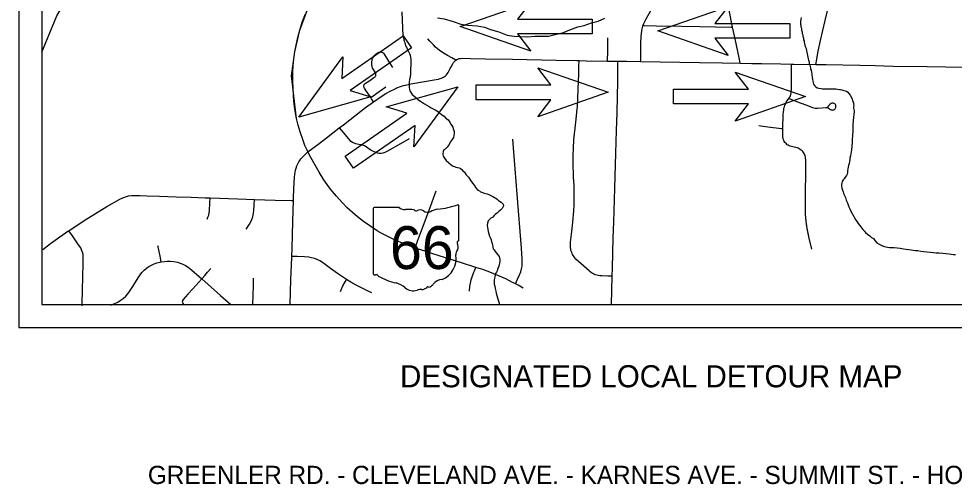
# Model space of a CAD drawing. Extents: x -483 to 680, y 0 to 440.
# Drawn here: x 436.4 to 580.4, y 219 to 290.7 of the extents above; entities that cross this region are included whole.
import ezdxf

# ---------------------------------------------------------------- set-up
doc = ezdxf.new("R2010")
doc.units = 0
for name, color, linetype in [('Default', 7, 'Continuous'), ('GM_X_City_Street', 7, 'Continuous'), ('GM_X_County_Road', 7, 'Continuous'), ('GM_X_Major_River', 7, 'Continuous'), ('GM_X_Minor_River', 7, 'Continuous'), ('GM_X_State_Route', 7, 'Continuous'), ('GM_X_State_Shield', 7, 'Continuous'), ('GM_X_Township_Road', 7, 'Continuous'), ('SH_Text', 7, 'Continuous')]:
    doc.layers.add(name, color=color, linetype=linetype)

msp = doc.modelspace()

# ---------------------------------------------------------------- linework, layer by layer
at = {"layer": 'Default'}
msp.add_lwpolyline([(436.43, 419.53), (436.43, 243.16), (629.12, 243.16), (629.12, 419.53)], close=True, dxfattribs=at)
msp.add_lwpolyline([(479.18, 275.33), (478.41, 281.87), (478.89, 285.56), (479.68, 288.94), (481.01, 292.52)], dxfattribs=at)
at = {"layer": 'GM_X_City_Street'}
msp.add_line((446.17, 246.5), (446.17, 246.58), dxfattribs=at)
for points in [[(532.11, 284.11), (532.12, 284.35), (532.14, 285.34), (532.14, 286.89), (532.19, 288), (532.23, 288.37), (532.29, 288.79), (532.35, 289.11), (532.41, 289.35), (532.51, 289.66), (532.63, 289.96), (532.98, 290.68), (533.88, 292.31), (534.84, 294.06), (535.27, 294.83), (536.17, 296.45), (539.57, 302.59), (540.98, 305.15), (542.08, 307.09), (542.51, 307.85), (544.46, 311.4), (545.32, 312.98), (546.62, 315.33), (547.54, 317.01)], [(547.44, 283.84), (547.26, 284.67), (546.66, 287.59), (546.27, 289.4), (545.72, 291.97), (544.63, 297.02), (544.39, 298.17), (543.75, 301.28), (543.31, 303.41), (542.7, 306.19), (542.62, 306.4), (542.51, 306.61), (542.24, 306.92), (542.08, 307.09)], [(559.05, 283.63), (559.1, 283.89), (559.44, 285.68), (559.8, 287.32), (560.51, 290.4), (561.5, 294.5), (561.68, 295.27)], [(532.51, 289.66), (532.65, 289.65), (534.52, 289.59), (538.36, 289.54), (541.22, 289.48), (546.02, 289.4), (546.27, 289.4)], [(503.67, 284.3), (503.09, 284.67), (502.41, 285.04), (501.78, 285.39), (501.44, 285.63), (501.18, 285.81), (500.82, 286.09), (500.56, 286.32), (500.23, 286.64), (500.03, 286.84), (499.69, 287.22), (499.38, 287.59)], [(527.04, 284.16), (527.04, 284.31), (527.07, 285.56), (527.09, 286.76), (527.07, 287.75)], [(490.6, 278.54), (489.76, 279.75), (489.62, 280.01), (489.57, 280.1), (489.54, 280.2), (489.53, 280.32), (489.54, 280.4), (489.56, 280.48), (489.59, 280.56), (489.65, 280.64), (490.45, 281.19), (491.07, 281.61), (491.25, 281.74), (491.31, 281.82), (491.35, 281.9), (491.38, 282), (491.38, 282.1), (491.37, 282.19), (491.35, 282.28), (491.33, 282.36), (490.99, 282.85), (490.86, 283.1), (490.82, 283.2), (490.79, 283.31), (490.76, 283.47), (490.75, 283.62), (490.74, 283.77), (490.75, 283.93), (490.75, 284.03), (490.77, 284.14), (490.79, 284.26), (490.83, 284.39), (490.88, 284.55), (490.94, 284.69), (491, 284.82), (491.06, 284.92), (491.12, 285), (491.2, 285.09), (491.28, 285.16), (491.4, 285.26), (491.85, 285.52), (491.96, 285.55), (492.06, 285.56), (492.14, 285.56), (492.24, 285.55), (492.33, 285.53), (492.42, 285.49), (492.48, 285.44), (492.57, 285.35), (493.94, 283.15)], [(527.74, 251.08), (527.07, 251.08), (526.14, 251.09), (525.87, 251.12), (525.62, 251.15), (525.38, 251.21), (525.14, 251.29), (524.93, 251.37), (524.75, 251.48), (524.56, 251.59), (524.36, 251.71), (524.17, 251.87), (522.14, 253.7), (521.99, 253.89), (521.87, 254.05), (521.76, 254.21), (521.63, 254.42), (521.56, 254.6), (521.47, 254.82), (521.39, 255.02), (521.35, 255.24), (521.32, 255.45), (521.3, 255.65), (521.3, 255.81), (521.32, 256.3), (521.51, 257.96), (521.66, 259.39), (521.82, 261.12), (521.88, 262.06), (521.9, 263.18), (521.87, 265.05), (521.81, 266.23), (521.73, 268.59), (521.74, 269.64), (521.77, 270.76), (521.86, 272.06), (522.14, 274.78), (522.29, 276.27), (522.36, 276.82), (522.38, 277.13), (522.52, 279.86), (522.59, 282.22), (522.62, 283.34), (522.66, 284.23)], [(527.61, 246.7), (527.74, 251.08), (527.77, 252.29), (527.91, 256.96), (527.99, 259.38), (528.16, 264.6), (528.31, 270.01), (528.4, 273.5), (528.5, 276.23), (528.62, 281.08), (528.63, 283.13), (528.63, 284.15)], [(558.48, 255.21), (558, 257.12), (557.99, 257.19), (557.97, 257.25), (557.96, 257.32), (557.94, 257.38), (557.93, 257.45), (557.91, 257.52), (557.9, 257.58), (557.88, 257.65), (557.87, 257.71), (557.86, 257.78), (557.84, 257.85), (557.83, 257.91), (557.82, 257.98), (557.8, 258.04), (557.79, 258.11), (557.78, 258.18), (557.77, 258.24), (557.75, 258.31), (557.74, 258.38), (557.73, 258.44), (557.72, 258.51), (557.71, 258.58), (557.7, 258.64), (557.69, 258.71), (557.68, 258.78), (557.67, 258.84), (557.66, 258.91), (557.65, 258.98), (557.64, 259.04), (557.63, 259.11), (557.62, 259.18), (557.61, 259.24), (557.6, 259.31), (557.59, 259.38), (557.59, 259.44), (557.58, 259.51), (557.57, 259.58), (557.56, 259.65), (557.56, 259.71), (557.55, 259.78), (557.54, 259.85), (557.54, 259.91), (557.53, 259.98), (557.52, 260.05), (557.52, 260.12), (557.51, 260.18), (557.51, 260.25), (557.5, 260.32), (557.5, 260.39), (557.5, 260.45), (557.49, 260.52), (557.49, 260.59), (557.48, 260.66), (557.48, 260.72), (557.48, 260.79), (557.47, 260.86), (557.47, 260.92), (557.47, 260.99), (557.47, 261.06), (557.46, 261.13), (557.46, 261.19), (557.46, 261.26), (557.46, 261.33), (557.46, 261.4), (557.46, 261.46), (557.46, 261.53), (557.46, 261.6), (557.46, 261.67), (557.46, 261.73), (557.46, 261.8), (557.46, 261.87), (557.46, 261.94), (557.46, 262), (557.52, 268.84), (557.48, 269.32), (557.41, 269.61), (557.35, 269.76), (557.27, 269.93), (557.17, 270.08), (557.06, 270.22), (556.96, 270.34), (556.81, 270.47), (556.68, 270.57), (556.52, 270.68), (556.35, 270.76), (556.2, 270.82), (555.55, 270.98), (555.12, 271.09), (554.96, 271.14), (554.82, 271.2), (554.67, 271.29), (554.55, 271.41), (554.32, 271.65), (554.21, 271.79), (554.15, 271.93), (554.09, 272.06), (554.03, 272.24), (554, 272.38), (553.98, 272.56), (553.99, 273.32), (554.01, 273.78), (554.06, 275.99), (554.08, 276.31), (554.13, 276.68), (554.17, 276.9), (554.23, 277.11), (554.3, 277.34), (554.41, 277.59), (554.52, 277.81), (554.66, 278.03), (554.93, 278.42), (555.05, 278.58), (555.17, 278.85), (555.22, 279.04), (555.26, 279.25), (555.29, 279.47), (555.31, 279.74), (555.35, 283.46), (555.35, 283.7)], [(490.6, 278.54), (490.97, 278.81), (491.88, 279.49), (492.92, 280.21)], [(491.03, 277.91), (490.71, 278.37), (490.6, 278.54)], [(554.93, 278.42), (555.08, 278.36), (556.64, 277.74), (557.67, 277.35), (558.55, 277.02), (558.74, 276.97), (558.96, 276.93), (559.14, 276.9), (559.32, 276.91), (560.62, 277.04), (560.83, 277.02), (561.03, 276.93), (561.35, 276.73), (561.44, 276.68), (561.53, 276.64), (561.62, 276.63), (561.74, 276.64), (561.85, 276.67), (561.93, 276.73), (562.02, 276.8), (562.11, 276.92), (562.14, 277), (562.16, 277.13), (562.16, 277.29), (562.14, 277.38), (562.1, 277.46), (562.01, 277.56), (561.88, 277.63), (561.77, 277.67), (561.66, 277.68), (561.53, 277.67), (561.41, 277.61), (561.28, 277.52), (561.19, 277.44), (561.11, 277.35), (561.01, 277.25), (560.85, 277.07)], [(485.73, 273.87), (486.33, 273.17), (487.17, 272.17), (487.39, 271.96), (487.62, 271.78), (487.88, 271.63), (488.22, 271.5), (488.75, 271.38), (489.12, 271.31), (489.43, 271.23), (489.73, 271.1), (490.11, 270.87), (490.66, 270.46), (490.98, 270.28), (491.31, 270.14), (491.6, 270.06), (491.89, 270.01), (492.19, 270.01), (492.48, 270.05), (492.83, 270.15), (493.21, 270.33), (495.21, 271.46), (496.55, 272.25)], [(550.31, 274.22), (550.61, 274.19), (551.71, 274.06), (553.8, 273.8), (554.01, 273.78)], [(512.85, 249.88), (513.18, 250.58), (513.5, 251.25), (513.67, 251.71), (513.8, 252.18), (513.87, 252.6), (513.9, 253.09), (513.88, 253.7), (513.77, 255.37), (513.12, 263.68), (512.81, 267.59), (512.6, 270.13), (512.47, 272.12)], [(440.12, 255.18), (441.31, 256.07), (442.73, 257.09), (444, 257.97), (444.14, 258.06), (446.49, 259.61), (448.23, 260.7), (449.98, 261.76), (451.98, 262.9), (452.47, 263.14), (452.87, 263.29), (453.34, 263.41), (453.76, 263.47), (454.25, 263.49), (455.05, 263.47), (456.17, 263.43), (458.1, 263.35), (460.64, 263.28), (462.94, 263.21), (465.11, 263.14), (465.86, 263.11), (470.15, 262.97), (472.68, 262.88), (475.86, 262.77), (478.42, 262.7), (478.71, 262.69)], [(497.4, 255.39), (497.8, 256.47), (498.39, 258.11), (499.56, 261.24), (500.68, 264.2)], [(465.4, 259.84), (465.52, 260.12), (465.66, 260.47), (465.75, 260.82), (465.79, 261.19), (465.83, 262.3), (465.86, 263.11)], [(471.44, 258.3), (471.95, 259.08), (472.13, 259.4), (472.3, 259.8), (472.43, 260.21), (472.56, 260.76), (472.62, 261.19), (472.65, 262.05), (472.68, 262.88)], [(446.17, 246.64), (446.23, 249.16), (446.27, 250.7), (446.35, 253.26), (446.36, 254.01), (446.33, 254.39), (446.24, 254.77), (446.11, 255.13), (445.96, 255.42), (445.65, 255.89), (444.69, 257.27), (444.14, 258.06)], [(458.36, 253.26), (458.18, 254.15), (457.89, 255.55), (457.85, 255.73)], [(450.61, 246.62), (450.8, 246.68), (451.2, 246.83), (451.69, 247.08), (452.06, 247.3), (452.5, 247.63), (452.91, 248), (453.19, 248.32), (453.48, 248.71), (453.98, 249.49), (454.78, 250.83), (455.1, 251.29), (455.39, 251.64), (455.74, 252), (456.09, 252.28), (456.45, 252.53), (456.85, 252.75), (457.25, 252.94), (457.68, 253.09), (458.17, 253.22), (458.36, 253.26), (458.85, 253.34), (459.29, 253.38), (459.74, 253.37), (460.3, 253.31), (460.86, 253.2), (461.29, 253.08), (461.7, 252.92), (462.1, 252.71), (462.52, 252.44), (463.02, 252.06), (464.59, 250.67), (467.47, 248.07), (469.04, 246.7)], [(490.75, 248.49), (490.2, 248.73), (488.37, 249.67), (487.55, 250.12), (486.86, 250.55), (486.38, 250.84), (485.45, 251.46), (484.38, 252.22), (483.15, 253.15), (482.74, 253.42), (482.36, 253.61), (481.96, 253.76), (481.49, 253.89), (481.07, 253.97), (480.4, 254.03), (479.28, 254.08), (479.03, 254.08), (478.44, 254.1)], [(464.59, 250.67), (465.04, 251.18), (465.49, 251.68), (465.98, 252.24)], [(505.78, 248.75), (505.78, 248.76), (505.84, 249.51), (505.92, 250.01), (506.04, 250.5), (506.25, 251.09), (506.47, 251.67), (506.55, 251.9), (506.74, 252.42)], [(464.59, 250.67), (463.2, 249.11), (462.45, 248.27), (461.75, 247.48), (461.65, 247.32), (461.61, 247.21), (461.6, 247.08), (461.63, 246.96), (461.8, 246.7)], [(472.44, 246.7), (472.54, 249.59), (472.54, 250.77)], [(485.96, 248.69), (486.04, 248.94), (486.31, 249.57), (486.66, 250.2), (486.86, 250.55)]]:
    msp.add_lwpolyline(points, dxfattribs=at)
at = {"layer": 'GM_X_County_Road'}
for points in [[(491.03, 277.91), (492.18, 278.69), (492.92, 279.15), (493.68, 279.58), (494.12, 279.81), (494.58, 280.02), (495.17, 280.24), (495.64, 280.39), (496.13, 280.52), (496.74, 280.66), (500.63, 281.3), (500.99, 281.37), (501.28, 281.46), (501.56, 281.58), (501.78, 281.68), (501.94, 281.79), (502.09, 281.91), (502.22, 282.04), (502.33, 282.19), (502.48, 282.39), (502.7, 282.81), (502.82, 283.01), (502.96, 283.29), (503.2, 283.72), (503.34, 283.94), (503.67, 284.3)], [(503.67, 284.3), (503.92, 284.43), (504.11, 284.5), (504.21, 284.53), (504.38, 284.56), (504.65, 284.59), (505.92, 284.57), (508.25, 284.52), (512.41, 284.43), (516.89, 284.33), (519.13, 284.29), (522.29, 284.24), (522.66, 284.23)], [(522.66, 284.23), (523.72, 284.2), (527.04, 284.16)], [(527.04, 284.16), (527.45, 284.15), (528.63, 284.15)], [(528.63, 284.15), (529.94, 284.15), (532.11, 284.11)], [(532.11, 284.11), (541.19, 283.95), (544.67, 283.88), (547.44, 283.84)], [(547.44, 283.84), (549.21, 283.81), (550.7, 283.77), (553.68, 283.73), (555.35, 283.7)], [(555.35, 283.7), (555.67, 283.69), (559.05, 283.63)], [(559.05, 283.63), (560.64, 283.61), (565.86, 283.51), (568.22, 283.46), (570.95, 283.4), (576.18, 283.32), (584.63, 283.16), (587.24, 283.1), (589.24, 283.03), (593.07, 282.9)], [(485.73, 273.87), (486.38, 274.37), (488.35, 275.89), (489.78, 276.99), (491.03, 277.91)], [(480.93, 270.18), (482.65, 271.47), (483.78, 272.34), (485.73, 273.87)]]:
    msp.add_lwpolyline(points, dxfattribs=at)
at = {"layer": 'GM_X_Major_River'}
for points in [[(439.96, 285.51), (442.31, 291.1), (442.99, 292.37), (443.71, 293.71), (444.39, 294.8), (444.99, 295.88), (445.55, 297), (446.07, 298.01), (446.59, 298.99)], [(500.86, 290.81), (501.88, 290.67), (503.28, 290.25), (504.44, 289.84), (505.5, 289.7), (506.94, 289.59), (508.07, 289.37), (509.04, 289.04), (510.32, 288.67), (511.56, 288.14), (512.66, 288), (513.68, 287.93), (514.66, 287.91), (515.84, 287.99), (516.98, 288), (517.96, 288.01), (518.96, 288.25), (520.25, 288.56), (521.21, 288.95), (522.47, 289.42), (523.43, 289.62), (524.58, 290.05), (525.57, 290.29), (526.61, 290.75)]]:
    msp.add_lwpolyline(points, dxfattribs=at)
at = {"layer": 'GM_X_Minor_River'}
for points in [[(495.38, 291.75), (495.51, 288.01), (495.62, 287.77), (495.68, 287.39), (495.75, 287.2), (495.82, 287.01), (495.89, 286.74), (495.96, 286.51), (496.07, 286.28), (496.18, 286.05), (496.28, 285.82), (496.46, 285.51), (496.54, 285.32), (496.64, 285.05), (496.71, 284.7), (496.74, 284.47), (496.76, 284.05), (496.75, 283.48), (496.73, 283.03), (496.72, 282.65), (496.71, 282.15), (496.66, 281.81), (496.62, 281.55), (496.57, 281.25), (496.52, 280.94), (496.51, 280.68), (496.51, 280.37), (496.5, 280.11), (496.53, 279.8), (496.6, 279.57), (496.96, 279.03), (497.22, 278.83), (497.52, 278.56), (497.85, 278.24), (498.26, 278), (498.56, 277.8), (498.86, 277.57), (499.23, 277.37), (499.57, 277.17), (499.9, 276.97), (500.2, 276.81), (500.5, 276.65), (500.76, 276.49), (500.99, 276.37), (501.17, 276.21), (501.43, 276.01), (501.65, 275.85), (501.88, 275.66), (502.1, 275.42), (502.32, 275.26), (502.51, 275.11), (502.76, 274.76), (502.87, 274.49), (503.05, 274.22), (503.2, 273.98), (503.3, 273.64), (503.4, 273.33), (503.43, 272.99), (503.39, 272.72), (503.3, 272.42), (502.98, 271.9), (502.82, 271.67), (502.66, 271.34), (502.35, 270.93), (502.03, 270.59), (501.84, 270.49), (501.72, 270.22), (501.67, 269.84), (501.74, 269.54), (501.92, 269.23), (502.21, 268.88), (502.54, 268.56), (502.95, 268.21), (503.25, 268.01), (503.48, 267.93), (503.7, 267.81), (503.96, 267.76), (504.19, 267.72), (504.38, 267.64), (504.6, 267.48), (504.75, 267.28), (505.01, 267.05), (505.26, 266.66), (505.63, 266.31), (505.89, 265.88), (506.1, 265.57), (506.29, 265.34), (506.43, 265.14), (506.65, 264.87), (506.69, 264.68), (507.09, 264.29), (507.32, 264.17), (507.5, 264.05), (507.69, 263.97), (508.03, 263.84), (508.25, 263.76)], [(556.82, 290.88), (556.78, 290.58), (556.73, 290.28), (556.72, 290.05), (556.72, 289.86), (556.75, 289.67), (556.78, 289.44), (556.85, 289.21), (556.88, 288.94), (556.95, 288.67), (556.98, 288.41), (557.05, 288.18), (557.08, 287.95), (557.15, 287.68), (557.18, 287.45), (557.25, 287.26), (557.28, 287.07), (557.45, 286.41), (557.56, 286.07), (557.63, 285.76), (557.69, 285.53), (557.72, 285.27), (557.79, 285), (557.82, 284.77), (557.89, 284.5), (557.96, 284.31), (558.03, 284.04), (558.06, 283.77), (558.13, 283.54), (558.2, 283.31), (558.23, 283.12), (558.26, 282.93), (558.34, 282.74), (558.4, 282.4), (558.43, 282.2), (558.47, 282.01), (558.53, 281.67), (558.56, 281.33), (558.59, 281.13), (558.66, 280.79), (558.73, 280.6), (558.84, 280.41), (559.06, 280.17), (559.28, 280.05), (559.51, 279.97), (559.89, 279.92)], [(559.89, 279.92), (560.11, 279.91), (560.34, 279.91), (560.57, 279.9), (560.91, 279.89), (561.29, 279.88), (561.52, 279.91), (562.13, 279.89), (562.39, 279.85), (562.69, 279.8), (562.88, 279.76), (563.07, 279.71), (563.37, 279.63), (563.56, 279.59), (563.79, 279.54), (564.01, 279.38), (564.16, 279.19), (564.34, 278.92), (564.56, 278.53), (564.66, 278.3), (564.73, 278.11), (564.84, 277.72), (564.87, 277.53), (564.9, 277.3), (564.89, 277.11), (564.89, 276.92), (564.92, 276.69), (564.95, 276.5), (564.95, 276.31), (564.94, 276.05), (564.93, 275.86), (564.89, 275.63), (564.84, 275.37), (564.8, 275.1), (564.79, 274.83), (564.78, 274.57), (564.77, 274.15), (564.76, 273.88), (564.75, 273.58), (564.74, 273.24), (564.7, 272.9), (564.69, 272.56), (564.68, 272.25), (564.67, 271.95), (564.66, 271.64), (564.55, 270.51), (564.5, 270.17), (564.46, 269.86), (564.41, 269.56), (564.32, 269.22), (564.28, 268.96), (564.23, 268.73), (564.19, 268.39), (564.1, 268.09), (564.06, 267.82), (564.01, 267.59), (563.96, 267.29), (563.92, 266.95), (563.87, 266.76), (563.79, 266.57), (563.59, 266.28), (563.43, 266.05), (563.28, 265.87), (563.12, 265.64), (563.07, 265.42), (563.03, 265.15), (563.02, 264.89), (563.05, 264.58), (563.16, 264.27), (563.26, 264.04), (563.33, 263.85), (563.4, 263.66), (563.55, 263.35), (563.62, 263.16), (563.69, 262.97), (563.76, 262.77), (563.9, 262.43), (564.04, 262.04), (564.15, 261.74), (564.29, 261.43), (564.43, 261.08), (564.94, 260.23), (565.08, 259.96), (565.23, 259.69), (565.41, 259.42), (565.59, 259.18), (565.77, 258.91), (565.99, 258.64), (566.14, 258.45), (566.29, 258.25), (566.54, 257.98), (566.73, 257.78), (567.02, 257.51), (567.36, 257.27), (567.66, 257.03), (567.92, 256.84), (568.13, 256.53), (568.47, 256.21), (568.84, 255.97), (569.14, 255.81), (569.33, 255.73)], [(508.25, 263.76), (508.52, 263.72), (508.74, 263.63), (508.97, 263.51), (509.19, 263.43), (509.38, 263.31), (509.64, 263.19), (509.83, 263.07), (510.02, 262.91), (510.2, 262.75), (510.42, 262.6), (510.65, 262.44), (510.98, 262.12), (511.01, 261.86), (510.81, 261.48), (510.57, 261.22), (510.3, 261), (510.03, 260.78), (509.8, 260.6), (509.6, 260.38), (509.37, 260.16), (509.06, 259.97), (508.86, 259.79), (508.66, 259.57), (508.54, 259.23), (508.49, 258.85), (508.56, 258.54), (508.59, 258.28), (508.66, 257.93), (508.76, 257.59), (508.86, 257.24), (509.01, 256.93), (509.11, 256.63), (509.18, 256.4), (509.29, 256.09), (509.32, 255.86), (509.38, 255.52), (509.45, 255.29), (509.56, 255.09), (509.71, 254.86), (509.93, 254.59), (510.15, 254.35), (510.33, 254.08), (510.4, 253.89), (510.43, 253.62), (510.46, 253.32), (510.32, 252.6), (510.16, 252.22), (510.04, 251.88), (509.92, 251.7), (509.8, 251.47), (509.71, 251.17), (509.67, 250.94), (509.63, 250.76), (509.58, 250.45), (509.57, 250.15), (509.6, 249.84), (509.67, 249.54), (509.73, 249.16), (509.83, 248.77), (509.9, 248.43), (510, 248.08), (510.38, 246.7)], [(569.33, 255.73), (569.63, 255.61), (569.82, 255.56), (570.12, 255.52), (570.38, 255.47), (570.61, 255.47), (570.84, 255.46), (571.14, 255.49), (571.56, 255.44), (572.05, 255.35), (572.54, 255.26), (572.96, 255.21), (573.37, 255.16), (574.43, 255.01), (574.78, 255), (575.23, 254.91), (575.68, 254.86), (576.17, 254.81), (576.67, 254.76), (577.12, 254.71), (577.58, 254.66), (578.07, 254.64), (578.6, 254.59), (579.09, 254.54), (579.58, 254.49), (580.19, 254.39), (580.57, 254.38)]]:
    msp.add_lwpolyline(points, dxfattribs=at)
at = {"layer": 'GM_X_State_Route'}
msp.add_lwpolyline([(514.04, 249.19), (513.25, 249.67), (512.85, 249.88), (512.42, 250.11), (511.35, 250.64), (510.15, 251.18), (508.93, 251.67), (507.81, 252.08), (506.74, 252.42), (504.55, 253.13), (500.12, 254.5), (498.44, 255.04), (497.4, 255.39), (497.04, 255.52), (495.49, 256.12), (494.35, 256.6), (493.41, 257.05), (492.38, 257.6), (491.58, 258.06), (490.45, 258.8), (489.49, 259.47), (488.57, 260.19), (487.76, 260.86), (486.95, 261.6), (486.17, 262.39), (485.3, 263.35), (484.41, 264.43), (483.38, 265.91), (482.65, 267.06), (482.02, 268.13), (481.36, 269.32), (480.93, 270.18), (480.8, 270.43), (480.47, 271.15), (480.17, 271.96), (479.74, 273.25), (479.42, 274.32), (479.18, 275.33), (479, 276.2), (478.91, 276.82), (478.76, 277.97), (478.69, 278.85), (478.63, 279.99), (478.6, 281.08), (478.6, 282.41), (478.64, 283.41), (478.75, 284.52), (478.89, 285.56), (479.09, 286.6), (479.37, 287.81), (479.68, 288.94), (480.05, 290.12), (480.55, 291.43)], dxfattribs=at)
at = {"layer": 'GM_X_State_Shield'}
for p, q in [((490.97, 261.46), (490.97, 251.45)), ((494.96, 261.63), (491.1, 261.63)), ((504.16, 256.64), (504.16, 261.88)), ((504.16, 256.64), (504.16, 256.64))]:
    msp.add_line(p, q, dxfattribs=at)
for centre, radius, start, end in [((499.46, 275.27), 13.98, 275.8445, 288.9065), ((504.01, 261.9), 0.147, 351.8621, 97.738), ((491.13, 261.48), 0.153, 98.1301, 188.1301), ((495.88, 262.79), 1.48, 231.6195, 271.1119), ((496.38, 256.01), 5.32, 80.4867, 94.9883), ((497.58, 261.53), 0.427, 219.7921, 297.1024), ((498.21, 260.37), 0.889, 54.4667, 119.1411), ((499.36, 261.96), 1.07, 233.8562, 294.8282), ((501.24, 258.57), 2.81, 97.3462, 120.7689), ((504.12, 256.26), 0.227, 107.944, 210.337), ((504, 256.62), 0.157, 289.6038, 7.7341), ((504.68, 254.45), 0.992, 136.8065, 186.9296), ((502.68, 255.6), 1.36, 340.033, 23.6496), ((500.24, 253.79), 3.5, 292.3089, 8.9858), ((491.13, 251.43), 0.154, 171.9584, 258.3066), ((491.15, 252.45), 1.18, 267.339, 280.6039), ((491.39, 250.87), 0.424, 29.7484, 93.2717), ((496.74, 259.86), 10.1, 240.4129, 257.1985), ((501.72, 248.64), 1.92, 94.4031, 142.5768), ((493.73, 246.96), 3.16, 47.1842, 75.836), ((497.15, 250.82), 2, 230.7004, 286.2918), ((498.45, 250.08), 1.07, 268.777, 315.5493), ((499.42, 249.11), 0.301, 65.7517, 132.6484), ((499.29, 250.48), 1.13, 282.8732, 323.2771), ((498.31, 247.37), 1.65, 85.6951, 111.2099)]:
    msp.add_arc(centre, radius, start, end, dxfattribs=at)
at = {"layer": 'GM_X_Township_Road'}
for points in [[(479.21, 268.03), (479.3, 268.24), (479.4, 268.46), (479.52, 268.65), (479.66, 268.86), (479.85, 269.1), (480, 269.26), (480.93, 270.18)], [(478.71, 262.69), (478.73, 263.07), (478.78, 264.56), (478.87, 266.28), (478.91, 266.69), (478.95, 267.06), (479.01, 267.38), (479.1, 267.68), (479.21, 268.03)], [(478.44, 254.1), (478.49, 255.31), (478.61, 259.47), (478.71, 262.69)], [(478.17, 246.7), (478.31, 250.53), (478.44, 253.88), (478.44, 254.1)]]:
    msp.add_lwpolyline(points, dxfattribs=at)
at = {"layer": 'SH_Text'}
for p, q in [((504.36, 289.47), (515.2, 293.23)), ((515.2, 293.23), (513.17, 290.59)), ((534.74, 288.8), (545.58, 292.57)), ((534.74, 288.8), (545.58, 292.57)), ((545.58, 292.57), (543.54, 289.93)), ((545.58, 292.57), (543.54, 289.93)), ((515.2, 285.7), (504.36, 289.47)), ((513.17, 290.59), (524.68, 290.59)), ((524.68, 290.59), (524.68, 288.34)), ((543.54, 289.93), (555.06, 289.93)), ((543.54, 289.93), (555.06, 289.93)), ((555.06, 289.93), (555.06, 287.68)), ((555.06, 289.93), (555.06, 287.68)), ((486.13, 281.5), (495.59, 288.06)), ((495.59, 288.06), (496.88, 286.21)), ((524.68, 288.34), (513.17, 288.34)), ((513.17, 288.34), (515.2, 285.7)), ((545.58, 285.04), (534.74, 288.8)), ((545.58, 285.04), (534.74, 288.8)), ((555.06, 287.68), (543.54, 287.68)), ((543.54, 287.68), (545.58, 285.04)), ((555.06, 287.68), (543.54, 287.68)), ((543.54, 287.68), (545.58, 285.04)), ((496.88, 286.21), (487.42, 279.64)), ((479.54, 275.55), (486.3, 284.82)), ((486.3, 284.82), (486.13, 281.5)), ((516.28, 283.11), (527.12, 279.35)), ((518.32, 280.48), (516.28, 283.11)), ((546.66, 282.45), (557.5, 278.69)), ((548.69, 279.82), (546.66, 282.45)), ((546.66, 282.45), (557.5, 278.69)), ((548.69, 279.82), (546.66, 282.45)), ((487.42, 279.64), (490.59, 278.64)), ((492.95, 277.13), (504, 280.22)), ((504, 280.22), (497.24, 270.94)), ((506.8, 278.22), (506.8, 280.48)), ((506.8, 280.48), (518.32, 280.48)), ((527.12, 279.35), (516.28, 275.59)), ((537.17, 277.56), (537.17, 279.82)), ((537.17, 279.82), (548.69, 279.82)), ((537.17, 277.56), (537.17, 279.82)), ((537.17, 279.82), (548.69, 279.82)), ((490.59, 278.64), (479.54, 275.55)), ((518.32, 278.22), (506.8, 278.22)), ((516.28, 275.59), (518.32, 278.22)), ((557.5, 278.69), (546.66, 274.93)), ((557.5, 278.69), (546.66, 274.93)), ((496.12, 276.12), (492.95, 277.13)), ((548.69, 277.56), (537.17, 277.56)), ((548.69, 277.56), (537.17, 277.56)), ((546.66, 274.93), (548.69, 277.56)), ((546.66, 274.93), (548.69, 277.56)), ((486.66, 269.55), (496.12, 276.12)), ((497.41, 274.27), (487.95, 267.7)), ((497.24, 270.94), (497.41, 274.27)), ((487.95, 267.7), (486.66, 269.55))]:
    msp.add_line(p, q, dxfattribs=at)
msp.add_lwpolyline([(439.96, 246.7), (625.59, 246.7), (625.59, 415.99), (439.96, 415.99)], close=True, dxfattribs=at)
msp.add_lwpolyline([(439.96, 246.7), (625.59, 246.7), (625.59, 415.99), (439.96, 415.99)], close=True, dxfattribs=at)

# ---------------------------------------------------------------- texts
at = {"layer": 'Default'}
msp.add_text('DESIGNATED LOCAL DETOUR MAP', height=3.4, dxfattribs=at).set_placement((495.09, 233.96))
at = {"layer": 'GM_X_State_Shield'}
msp.add_text('66', height=6.592, dxfattribs=at).set_placement((493.55, 252.16))
at = {"layer": 'SH_Text'}
msp.add_text('GREENLER RD. - CLEVELAND AVE. - KARNES AVE. - SUMMIT ST. - HOPKINS ST. - 5TH ST.', height=2.8, dxfattribs=at).set_placement((456.3, 219.08))

doc.saveas('drawing.dxf')
